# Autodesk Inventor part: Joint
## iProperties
Shininess: 69.0
Length Units: 11269
Angle Units: 11279
Time Units: 11290
Mass Units: 11283
Length Display Precision: 3
Angle Display Precision: 2
Created: 2001-04
Part Number: Joint
Material: Standard
Document SubType Name: Modellieren
Designer: dl
Density: 1 g/cm^3
Density: 0.0
Volumn: 0.0
Area: 0.0
PropertySet Name: Model Information
Control State: 0
Master: False
Checked Out: False
Author: dl
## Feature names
1. Revolution1
2. Extrusion1
3. Revolution2
4. Hole1
5. Chamfer1
6. Chamfer2
7. Fillet1
